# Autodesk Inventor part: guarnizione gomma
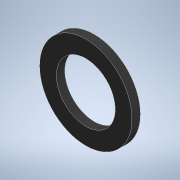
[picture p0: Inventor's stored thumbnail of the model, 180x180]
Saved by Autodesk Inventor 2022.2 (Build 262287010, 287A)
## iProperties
Created: 2022-03
Part Number: guarnizione gomma
Material: Gomma
Document SubType Name: Modeling
Designer: 18619647
Density: 0.93 g/cm^3
Appearance: Gomma - Nero
Author: 18619647
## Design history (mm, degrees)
sketch "Schizzo1"
  geometry: C1 r 8.25 at (0, 0); C2 r 5.25 at (0, 0); 1 further point
  constraints: 2 centre point, 2 coincident
  dimensions: "d0" = 16.5 diameter of C1; "d1" = 10.5 diameter of C2
extrude "Estrusione1" new body sketch "Schizzo1" distance "d2" = 1.5; taper "d3" = 0 deg
node "Solido1"
